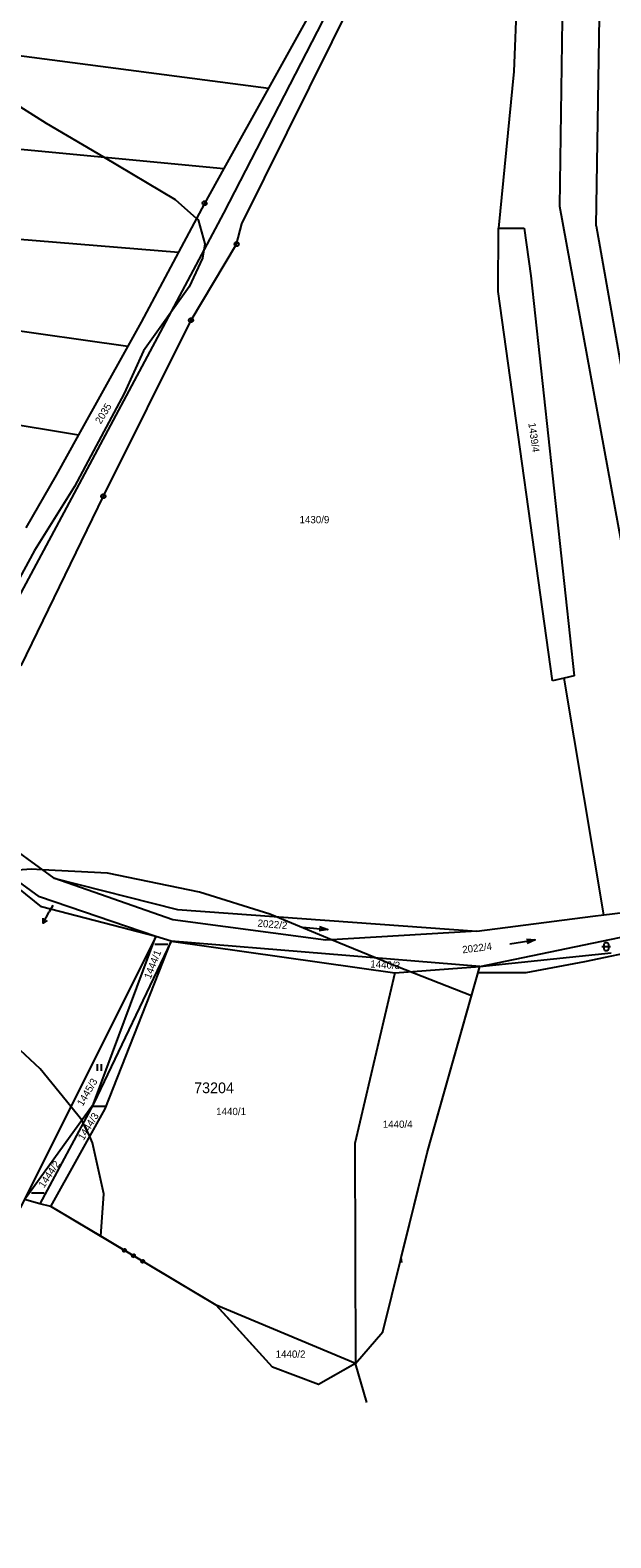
# Model space of a CAD drawing. Extents: x -789470 to -786707, y -1118640 to -1114455.
# Drawn here: x -787215.8 to -787080.3, y -1118639.5 to -1118287.5 of the extents above; entities that cross this region are included whole.
import ezdxf

# ---------------------------------------------------------------- set-up
doc = ezdxf.new("R2010")
doc.units = 0
for name, color, linetype in [('1', 7, 'Continuous'), ('11', 7, 'Continuous'), ('2', 7, 'Continuous'), ('3', 7, 'Continuous'), ('6', 7, 'Continuous'), ('7', 7, 'Continuous'), ('8', 7, 'Continuous')]:
    doc.layers.add(name, color=color, linetype=linetype)

msp = doc.modelspace()

# ---------------------------------------------------------------- linework, layer by layer
at = {"layer": '1'}
for p, q in [((-787083.67, -1118333.2), (-787080.45, -1118134.14)), ((-787089.51, -1118139.72), (-787092.27, -1118328.55)), ((-787097.88, -1118167.47), (-787102.87, -1118297.16)), ((-787166.34, -1118332.73), (-787139.65, -1118278.87)), ((-787150.06, -1118282.8), (-787160.15, -1118301.02)), ((-787243.13, -1118290.18), (-787160.15, -1118301.02)), ((-787102.87, -1118297.16), (-787106.5, -1118333.7)), ((-787160.15, -1118301.02), (-787170.53, -1118319.75)), ((-787225.85, -1118314.51), (-787170.53, -1118319.75)), ((-787170.53, -1118319.75), (-787175.05, -1118327.91)), ((-787175.05, -1118327.91), (-787181.11, -1118339.31)), ((-787092.27, -1118328.55), (-787062.37, -1118491.63)), ((-787167.59, -1118337.44), (-787166.34, -1118332.73)), ((-787106.57, -1118348.47), (-787106.5, -1118333.7)), ((-787106.5, -1118333.7), (-787100.5, -1118333.72)), ((-787100.5, -1118333.72), (-787098.9, -1118344.83)), ((-787083.67, -1118333.2), (-787055.86, -1118490.84)), ((-787219.07, -1118336.16), (-787181.11, -1118339.31)), ((-787178.21, -1118355.17), (-787167.59, -1118337.44)), ((-787181.11, -1118339.31), (-787189.82, -1118355.68)), ((-787098.9, -1118344.83), (-787088.78, -1118438.18)), ((-787093.84, -1118439.41), (-787106.57, -1118348.47)), ((-787256.87, -1118352.13), (-787192.93, -1118361.27)), ((-787198.68, -1118396.25), (-787178.21, -1118355.17)), ((-787189.82, -1118355.68), (-787192.93, -1118361.27)), ((-787192.93, -1118361.27), (-787204.45, -1118381.96)), ((-787288.56, -1118368.12), (-787204.45, -1118381.96)), ((-787204.45, -1118381.96), (-787209.71, -1118391.41)), ((-787209.71, -1118391.41), (-787216.75, -1118403.66)), ((-787217.86, -1118435.86), (-787198.68, -1118396.25)), ((-787091.16, -1118438.76), (-787093.84, -1118439.41)), ((-787088.78, -1118438.18), (-787091.16, -1118438.76)), ((-787081.87, -1118493.99), (-787091.16, -1118438.76)), ((-787235.39, -1118467.18), (-787210.21, -1118485.49)), ((-787213.6, -1118489.81), (-787240.28, -1118470.25)), ((-787213.08, -1118492.14), (-787240.28, -1118470.25)), ((-787182.49, -1118495.22), (-787210.21, -1118485.49)), ((-787210.21, -1118485.49), (-787181.36, -1118492.77)), ((-787186.43, -1118499.08), (-787213.6, -1118489.81)), ((-787186.43, -1118499.08), (-787213.08, -1118492.14)), ((-787181.36, -1118492.77), (-787111.53, -1118497.85)), ((-787081.87, -1118493.99), (-787062.37, -1118491.63)), ((-787146.75, -1118499.9), (-787182.49, -1118495.22)), ((-787111.53, -1118497.85), (-787084.45, -1118494.3)), ((-787110.85, -1118506.06), (-787053.4, -1118494.16)), ((-787084.45, -1118494.3), (-787081.87, -1118493.99)), ((-787186.43, -1118499.08), (-787217.11, -1118560.49)), ((-787200.96, -1118538.1), (-787186.43, -1118499.08)), ((-787182.84, -1118500.19), (-787200.96, -1118538.1)), ((-787198.25, -1118539.29), (-787182.84, -1118500.19)), ((-787182.84, -1118500.19), (-787186.43, -1118499.08)), ((-787182.84, -1118500.19), (-787130.65, -1118507.57)), ((-787110.85, -1118506.06), (-787182.84, -1118500.19)), ((-787111.53, -1118497.85), (-787146.75, -1118499.9)), ((-787110.85, -1118506.06), (-787080.17, -1118502.89)), ((-787130.65, -1118507.57), (-787110.85, -1118506.06)), ((-787123.11, -1118549.59), (-787110.85, -1118506.06)), ((-787130.65, -1118507.57), (-787140.02, -1118547.36)), ((-787217.11, -1118560.49), (-787200.96, -1118538.1)), ((-787200.96, -1118538.1), (-787213.48, -1118561.45)), ((-787210.97, -1118562.12), (-787198.25, -1118539.29)), ((-787140.02, -1118547.36), (-787139.82, -1118598.75)), ((-787133.46, -1118591.34), (-787123.11, -1118549.59)), ((-787213.48, -1118561.45), (-787217.11, -1118560.49)), ((-787210.97, -1118562.12), (-787213.48, -1118561.45)), ((-787172.32, -1118585.11), (-787210.97, -1118562.12)), ((-787159.24, -1118599.65), (-787172.32, -1118585.11)), ((-787139.82, -1118598.75), (-787172.32, -1118585.11)), ((-787139.82, -1118598.75), (-787133.46, -1118591.34)), ((-787139.82, -1118598.75), (-787148.47, -1118603.68)), ((-787137.18, -1118607.84), (-787139.82, -1118598.75)), ((-787148.47, -1118603.68), (-787159.24, -1118599.65))]:
    msp.add_line(p, q, dxfattribs=at)
for points in [[(-787194.09, -1118572.54), (-787194.15, -1118572.27), (-787194.01, -1118572.04), (-787193.75, -1118571.98), (-787193.52, -1118572.11), (-787193.46, -1118572.38), (-787193.59, -1118572.61), (-787193.85, -1118572.67), (-787194.09, -1118572.54), (-787194.03, -1118572.52), (-787193.83, -1118572.64), (-787193.73, -1118572.61), (-787194.06, -1118572.41), (-787194.09, -1118572.3), (-787193.64, -1118572.57), (-787193.6, -1118572.5), (-787194.05, -1118572.23), (-787194.01, -1118572.16), (-787193.56, -1118572.43), (-787193.51, -1118572.37), (-787193.96, -1118572.1), (-787193.88, -1118572.05), (-787193.53, -1118572.26), (-787193.53, -1118572.17), (-787193.74, -1118572.05)], [(-787191.93, -1118573.82), (-787192, -1118573.56), (-787191.86, -1118573.33), (-787191.6, -1118573.26), (-787191.36, -1118573.4), (-787191.3, -1118573.66), (-787191.44, -1118573.89), (-787191.7, -1118573.96), (-787191.93, -1118573.82), (-787191.9, -1118573.79), (-787191.69, -1118573.91), (-787191.58, -1118573.88), (-787191.93, -1118573.68), (-787191.96, -1118573.57), (-787191.47, -1118573.86), (-787191.43, -1118573.79), (-787191.91, -1118573.5), (-787191.87, -1118573.43), (-787191.39, -1118573.72), (-787191.35, -1118573.65), (-787191.83, -1118573.36), (-787191.72, -1118573.34), (-787191.38, -1118573.54), (-787191.41, -1118573.43), (-787191.61, -1118573.31)], [(-787189.77, -1118575.1), (-787189.84, -1118574.84), (-787189.7, -1118574.61), (-787189.44, -1118574.54), (-787189.21, -1118574.68), (-787189.14, -1118574.94), (-787189.28, -1118575.17), (-787189.54, -1118575.24), (-787189.77, -1118575.1), (-787189.76, -1118575.06), (-787189.55, -1118575.18), (-787189.44, -1118575.16), (-787189.79, -1118574.95), (-787189.8, -1118574.85), (-787189.33, -1118575.13), (-787189.29, -1118575.06), (-787189.75, -1118574.79), (-787189.72, -1118574.72), (-787189.26, -1118574.99), (-787189.22, -1118574.92), (-787189.68, -1118574.65), (-787189.59, -1118574.6), (-787189.22, -1118574.82), (-787189.24, -1118574.72), (-787189.48, -1118574.58)]]:
    msp.add_lwpolyline(points, dxfattribs=at)
at = {"layer": '11'}
for points in [[(-787316.1, -1118256.91), (-787247.04, -1118288.28), (-787243.88, -1118290.06), (-787230.33, -1118297.66), (-787211.99, -1118309.19), (-787198.67, -1118317.08), (-787181.95, -1118326.99), (-787176.94, -1118331.46), (-787176.56, -1118331.8), (-787175.02, -1118337.35), (-787175.54, -1118340.72), (-787178.69, -1118347.39), (-787189.28, -1118362.31), (-787193.8, -1118372.33), (-787200.96, -1118385.66), (-787205.43, -1118393.99), (-787214.75, -1118408.94), (-787230.84, -1118438.51)], [(-787112.79, -1118512.95), (-787130.07, -1118506.17), (-787135.15, -1118504.08), (-787145.45, -1118499.82), (-787158.51, -1118494.43), (-787159.84, -1118493.88), (-787176.24, -1118488.75), (-787197.75, -1118484.31), (-787212.94, -1118483.51), (-787215.54, -1118483.37), (-787221.72, -1118483.85), (-787223.23, -1118483.97), (-787231.26, -1118484.6), (-787244.06, -1118487.19), (-787250.3, -1118490.41), (-787255.68, -1118493.19)], [(-787199.3, -1118569.06), (-787198.55, -1118559.16), (-787201.19, -1118547.24), (-787201.87, -1118545.79), (-787203.36, -1118542.58), (-787203.59, -1118542.09), (-787203.72, -1118541.93), (-787206.27, -1118538.79), (-787213.43, -1118529.96), (-787220.46, -1118523.41), (-787235.48, -1118514.51), (-787244.7, -1118510.43), (-787254.95, -1118507.27), (-787259.84, -1118505.76), (-787258.42, -1118500.3), (-787256.65, -1118497.82), (-787255.68, -1118493.19)], [(-787112.79, -1118512.95), (-787111.25, -1118507.47), (-787099.99, -1118507.48), (-787086.35, -1118504.92), (-787072.27, -1118501.94), (-787062.86, -1118498.84)], [(-787129.01, -1118575.16), (-787129.16, -1118574.01), (-787123.11, -1118549.59), (-787112.79, -1118512.95)], [(-787199.3, -1118569.06), (-787210.97, -1118562.12), (-787213.48, -1118561.45), (-787217.11, -1118560.49), (-787255.19, -1118633.7), (-787257, -1118636.34), (-787259.14, -1118639.46), (-787272.02, -1118631.21), (-787314.06, -1118611.19), (-787319.31, -1118608.45), (-787324.12, -1118605.87), (-787365.06, -1118588.3), (-787379.56, -1118581.78), (-787407.83, -1118581.15), (-787432.67, -1118576.48)], [(-787139.76, -1118598.97), (-787139.82, -1118598.75), (-787140.03, -1118598.87), (-787148.47, -1118603.68), (-787159.24, -1118599.65), (-787169.76, -1118587.95), (-787172.32, -1118585.11), (-787199.3, -1118569.06)]]:
    msp.add_lwpolyline(points, dxfattribs=at)
at = {"layer": '3'}
for p, q in [((-787152.24, -1118496.93), (-787146.26, -1118497.41)), ((-787103.8, -1118500.8), (-787097.88, -1118499.88)), ((-787186.65, -1118500.86), (-787183.65, -1118500.86)), ((-787200.12, -1118528.91), (-787200.12, -1118530.41)), ((-787199.12, -1118530.41), (-787199.12, -1118528.91)), ((-787201.13, -1118538.67), (-787198.13, -1118538.67)), ((-787215.48, -1118558.92), (-787212.48, -1118558.92))]:
    msp.add_line(p, q, dxfattribs=at)
for points in [[(-787148.21, -1118496.75), (-787146.26, -1118497.41), (-787148.29, -1118497.75)], [(-787099.93, -1118499.69), (-787097.88, -1118499.88), (-787099.78, -1118500.68)], [(-787082.34, -1118501.44), (-787081.07, -1118501.44), (-787080.34, -1118501.44)]]:
    msp.add_lwpolyline(points, dxfattribs=at)
msp.add_lwpolyline([(-787081.84, -1118500.94), (-787081.74, -1118500.65), (-787081.49, -1118500.47), (-787081.18, -1118500.47), (-787080.93, -1118500.65), (-787080.83, -1118500.94), (-787080.83, -1118501.94), (-787080.93, -1118502.23), (-787081.18, -1118502.41), (-787081.49, -1118502.41), (-787081.74, -1118502.23), (-787081.84, -1118501.94)], close=True, dxfattribs=at)
at = {"layer": '6'}
for p, q in [((-787170.59, -1118330.2), (-787144.79, -1118280.17)), ((-787184.71, -1118356.82), (-787170.59, -1118330.2)), ((-787204.25, -1118393.43), (-787184.71, -1118356.82)), ((-787222.61, -1118427.68), (-787204.25, -1118393.43))]:
    msp.add_line(p, q, dxfattribs=at)
at = {"layer": '7'}
for p in [(-787210.45, -1118491.8), (-787212.74, -1118495.93)]:
    msp.add_line(p, (-787211.29, -1118493.31), dxfattribs=at)
msp.add_lwpolyline([(-787211.82, -1118495.3), (-787212.74, -1118495.93), (-787212.7, -1118494.82)], dxfattribs=at)
at = {"layer": '8'}
for p, q in [((-787175.17, -1118327.91), (-787174.93, -1118327.91)), ((-787167.71, -1118337.44), (-787167.47, -1118337.44)), ((-787178.33, -1118355.17), (-787178.09, -1118355.17)), ((-787198.8, -1118396.25), (-787198.56, -1118396.25))]:
    msp.add_line(p, q, dxfattribs=at)
for points in [[(-787174.9, -1118327.43), (-787174.65, -1118327.61), (-787174.55, -1118327.9), (-787174.65, -1118328.19), (-787174.9, -1118328.37), (-787175.21, -1118328.37), (-787175.46, -1118328.19), (-787175.56, -1118327.9), (-787175.46, -1118327.61), (-787175.21, -1118327.43)], [(-787167.44, -1118336.96), (-787167.19, -1118337.14), (-787167.09, -1118337.43), (-787167.19, -1118337.72), (-787167.44, -1118337.9), (-787167.75, -1118337.9), (-787168, -1118337.72), (-787168.1, -1118337.43), (-787168, -1118337.14), (-787167.75, -1118336.96)], [(-787178.06, -1118354.69), (-787177.81, -1118354.87), (-787177.71, -1118355.16), (-787177.81, -1118355.45), (-787178.06, -1118355.63), (-787178.37, -1118355.63), (-787178.62, -1118355.45), (-787178.72, -1118355.16), (-787178.62, -1118354.87), (-787178.37, -1118354.69)], [(-787198.53, -1118395.77), (-787198.28, -1118395.95), (-787198.18, -1118396.24), (-787198.28, -1118396.53), (-787198.53, -1118396.71), (-787198.84, -1118396.71), (-787199.09, -1118396.53), (-787199.19, -1118396.24), (-787199.09, -1118395.95), (-787198.84, -1118395.77)]]:
    msp.add_lwpolyline(points, close=True, dxfattribs=at)

# ---------------------------------------------------------------- texts
at = {"layer": '11'}
msp.add_text('73204', height=2.5, dxfattribs=at).set_placement((-787177.5, -1118535.65))
at = {"layer": '2'}
for s, rotation, p in [('1439/4', 278.0564, (-787099.51, -1118379.25)), ('2022/2', 355.0619, (-787162.75, -1118496.76)), ('1444/1', 68.4685, (-787187.67, -1118509.12)), ('2022/4', 7.1047, (-787114.82, -1118503.02)), ('1440/3', 356.7235, (-787136.42, -1118506.31)), ('1445/3', 59.3584, (-787203.5, -1118538.83)), ('1444/3', 58.4417, (-787203.3, -1118546.8)), ('1444/2', 56.3218, (-787212.54, -1118557.92))]:
    msp.add_text(s, height=1.7, rotation=rotation, dxfattribs=at).set_placement(p)
for s, height, p in [('1430/9', 1.7, (-787152.9, -1118402.6)), ('2022/3', 0.1, (-787210.71, -1118491.8)), ('1440/1', 1.7, (-787172.35, -1118540.77)), ('1440/4', 1.7, (-787133.47, -1118543.74)), ('1440/2', 1.7, (-787158.47, -1118597.42))]:
    msp.add_text(s, height=height, dxfattribs=at).set_placement(p)
at = {"layer": '7'}
msp.add_text('2035', height=1.7, rotation=58.7282, dxfattribs=at).set_placement((-787199.29, -1118379.57))

doc.saveas('drawing.dxf')
